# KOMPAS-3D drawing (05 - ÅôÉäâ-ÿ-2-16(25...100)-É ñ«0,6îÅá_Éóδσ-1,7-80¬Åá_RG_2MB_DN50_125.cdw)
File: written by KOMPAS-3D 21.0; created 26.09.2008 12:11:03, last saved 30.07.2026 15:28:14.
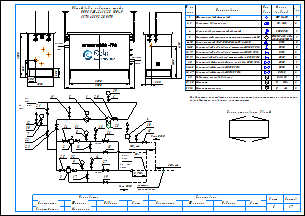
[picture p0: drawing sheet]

Sheets 1-2: A3, landscape

Document properties: Наименование: Макро:21; Автор: RaskoAdmin; Форматы листов документа: 2xA3; Полное имя файла: \\ur38nt01\Departments\КТО\КБ ПУРДГ\Заявки\Прайс-лист на типовые шкафы ГРПШ\ПУРДГ_стандарт_30_04_2026\ПУРДГ с RG_2MB\ПУРДГ-Ш-2-16(25...100)-Р до0,6МПа_Рвых-1,7-80кПа_RG_2MB_DN50_125.cdw

Title block, sheet 1: Наименование: Пункт учета газа / ПУГ-Ш-400-Р / ЛГТИ.485922.001ТУ; designation: ЛГТИ.03.4411141; sheet number: 1; Количество листов документа: 2; organisation: ООО "ЭЛЬСТЕР Газэлектроника"; Форматы листов документа: A3; stored path: C:\Рабочие документы\Компас\ПУГ\Схема.cdw; Разработал: Устинов; Проверил: Кошкин; Утвердил: Кошкин
Title block, sheet 2: sheet number: 2; stored path: D:\Рабочие документы\Заявки\ПУРДГ\ПУРДГ-ШУЭО-2-100-Р 4411220.cdw; designation, second copy: ЛГТИ.03.4411141-

Views: Вид 1, Вид 2
Referenced files: wcvoit.frw
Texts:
  Normal
  № на
  схеме
  Усл.
  обозн.
  Марка
  (модель)
  Кол.
  Фильтр газовый фланцевый
  ФГ 16-50
  Регулятор давления газа
  RG/2MB
  Клапан предохранительный сбросной
  КПС DN20
  Измерительный комплекс с ротационным счетчиком Ду50
  СГ-ЭК-Р-(0,2...2,0)-
  Кран кнопочный VE-РАСКО-НЗ-1,6-G1/2-М20
  DN15
  Кран шаровой "под приварку" штуцерный DN20 PN16
  DN20
  Кран шаровой "под приварку" штуцерный DN15 PN16
  Кран шаровой "под приварку" штуцерный п/п DN20 PN16
  Кран шаровой фланцевый с мех. приводом DN50 PN16
  Кран шаровой фланцевый DN50 PN16
  Кран шаровой фланцевый DN125 PN16
  DN50
  DN125
  Индикатор перепада давления
  Манометр
  Манометр-напоромер
  Delta 15
  0...     МПа
  0...     кПа
  Общий вид и габариты шкафа
  ПУРДГ-Ш-2-16(25...100)-Р
  Выход газа
  Вход газа
  logo-rasko-ge.png
  DN 1
  местное
  сопротивление
  Римп DN20
  Выход
  газа
  Р=     кПа
  Вход
  Р=       МПа
  PDI
  Схема открывания дверей
  Предприятие изготовитель может заменять комплектующие на аналогичные,
  не ухудшающие заявленных характеристик.
  Должность
  Конструктор
  Фамилия
  Подпись
  Дата
  Согласовано
  Максимкин
  Лист
  Листов
  POLYLINE_STYLE_0.18_RGB_0_0_0
  POLYLINE_STYLE_0.50_RGB_0_0_0
  POLYLINE_STYLE_0.34_RGB_0_0_0
  PHANTOM_RGB_0_0_0_SC_1_THICK_0.18
  K5LT_THIN_RGB_0_0_0_THICK_0.18
  K5LT32769_RGB_0_0_0_THICK_0.18
  K5LT12_RGB_0_0_0_SC_1_THICK_0.18
  K5LT_DASHED_RGB_0_0_0_SC_1_THICK_0.18
  ACISOTGL_RGB_0_0_0_SC_0.8_THICK_0.25
  CONTINUOUS_RGB_0_127_31_THICK_0.3
  CONTINUOUS_RGB_0_0_255_THICK_0.35
  CONTINUOUS_RGB_255_0_0_THICK_0.35
  POLYLINE_STYLE_0.25_RGB_0_0_0
  CONTINUOUS_RGB_0_0_0_THICK_0.5
  POLYLINE_STYLE_0.35_RGB_0_0_255
  CONTINUOUS_RGB_0_0_0_THICK_0.4
  CONTINUOUS_RGB_0_0_0_THICK_0.35
  НЕВИДИМАЯ_RGB_0_0_0_SC_0.3_THICK_0.25
  СONTINUOUS_RGB_0_0_0_THICK_0.25
  ОСЕВАЯ2_RGB_248_153_30_SC_0.3_THICK_0.25
  Без оформления
Dimensions and other numbers on the sheet: 1; 2, 3; 2; 4; 5; 6-10; 11-15; 16, 17; 18, 19; 20; 21-25; 26, 27; 28; 29, 30; 31, 32; 1500; 250; 300; 1050; 550; 305; 2500; 4130; 2000; 2800; 5,,,7DN 1; 7; 30; 12; 21; 22; 23; 11; 6; 29; 24; 31; 8; 16; 13; 26; 18; 10; 15; 25; 32; 9; 3; 17; 14; 27; 19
